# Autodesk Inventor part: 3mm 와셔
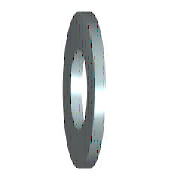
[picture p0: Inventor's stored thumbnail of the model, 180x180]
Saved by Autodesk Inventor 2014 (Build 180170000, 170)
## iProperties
Created: 2012-02
Part Number: 3mm 와셔
Material: 스테인리스강
Description: 평면 와셔 - 대형 시리즈 - 제품 등급 A
Document SubType Name: Modeling
Standard: ISO 7093 A
Designer: mduedu
Standard Revision: First Edition 2000-06-01
Standards Organization: ISO
Language: ko-KR
Size Designation: ST 3 - 140 HV - A
Categories: <MemberInstance><Categories><Category DisplayName="조임쇠" InternalName="e4da775c-781d-43d5-af7c-5136215cf5a6" Mnemonic="FSTN"><Category DisplayName="와셔" InternalN
Density: 8.08 g/cm^3
Appearance: 파란색 - 벽 페인트 - 광택
IsCustomPart: 1
Author: mduedu
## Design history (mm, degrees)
sketch "스케치"
  geometry: C1 r 4.5 at (0, 0); C2 r 1.6 at (0, 0); 1 further point
  constraints: 2 centre point, 2 coincident
  dimensions: "d0" = 3.2 diameter of C2 (= SD1); "d1" = 9 diameter of C1 (= SD2)
extrude "본체" new body sketch "스케치" distance "d2" = 0.8 (= SD); taper "d3" = 0 deg
workaxis "Work Axis1"
workplane "Work Plane1"
sketch "스케치5"
  geometry: 2 further points
  constraints: 1 coincident
body "Solid1"
other parameters: "SD1" = 3.2 [user parameter; used in 1 equation term], "SD2" = 9 [user parameter; used in 1 equation term], "SD" = 0.8 [user parameter; used in 1 equation term], "d4" = 0, "d5" = 0, "d6" = 0, "d7" = 0, "NND" = 3 [user parameter]
